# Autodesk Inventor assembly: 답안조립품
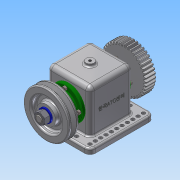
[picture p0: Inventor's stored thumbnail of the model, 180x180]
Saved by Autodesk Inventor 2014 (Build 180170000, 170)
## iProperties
Created: 2018-11
Part Number: 답안조립품
Document SubType Name: Assembly
Designer: 703
Author: 703
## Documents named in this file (14)
- C:\Users\user\Desktop\481107V1019\답안조립품.iam
- C:\Users\user\Desktop\481107V1019\본체.ipt
- C:\Users\user\Desktop\481107V1019\V벨트풀리.ipt
- C:\Users\user\Desktop\481107V1019\너트 M12x1.25.ipt
- C:\Users\user\Desktop\481107V1019\베어링 6203.ipt
- C:\Users\user\Desktop\481107V1019\볼트 M4.ipt
- C:\Users\user\Desktop\481107V1019\부시.ipt
- C:\Users\user\Desktop\481107V1019\스퍼기어.ipt
- C:\Users\user\Desktop\481107V1019\오일 실 26 38 8.ipt
- C:\Users\user\Desktop\481107V1019\와셔 12x24.ipt
- C:\Users\user\Desktop\481107V1019\축.ipt
- C:\Users\user\Desktop\481107V1019\커버.ipt
- C:\Users\user\Desktop\481107V1019\키 5x5x12.ipt
- C:\Users\user\Desktop\481107V1019\부시_MIR.ipt
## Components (1 placed, 1 different names)
1. V벨트풀리:1
## Named parameters: d24_d22 = 0
